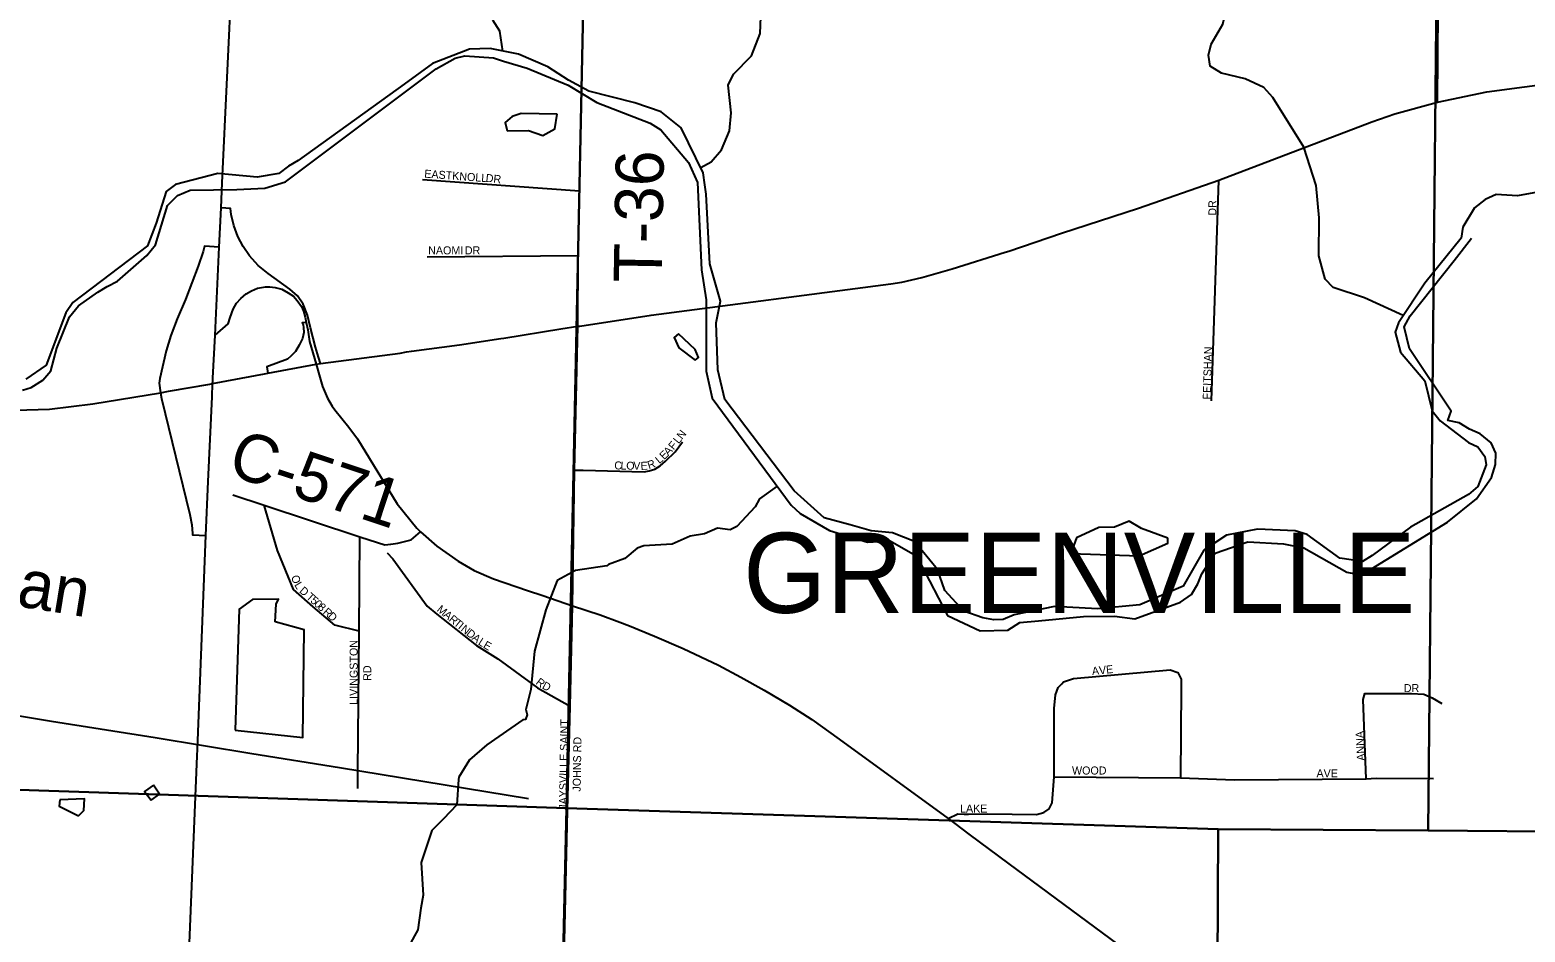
# Model space of a CAD drawing. Extents: x -784 to 1375, y -225 to 440.
# Drawn here: x 321.44 to 357.92, y 339.88 to 361.88 of the extents above; entities that cross this region are included whole.
import ezdxf

# ---------------------------------------------------------------- set-up
doc = ezdxf.new("R2010")
doc.units = 0
for name, color, linetype in [('GM_X_City_Street', 7, 'Continuous'), ('GM_X_City_Street_Text', 7, 'Continuous'), ('GM_X_Corporation_Text', 7, 'Continuous'), ('GM_X_County_Road', 7, 'Continuous'), ('GM_X_County_Road_Text', 7, 'Continuous'), ('GM_X_Interchange_Ramps', 7, 'Continuous'), ('GM_X_Major_River', 7, 'Continuous'), ('GM_X_Minor_Lake', 7, 'Continuous'), ('GM_X_Minor_River', 7, 'Continuous'), ('GM_X_Rail_Line', 7, 'Continuous'), ('GM_X_Rail_Line_Text', 7, 'Continuous'), ('GM_X_Section', 7, 'Continuous'), ('GM_X_State_Route', 7, 'Continuous'), ('GM_X_Township_Road', 7, 'Continuous'), ('GM_X_Township_Road_Text', 7, 'Continuous'), ('GM_X_Township_Subdivision', 7, 'Continuous'), ('GM_X_Township_Subdivision_Text', 7, 'Continuous'), ('GM_X_US_Route', 7, 'Continuous')]:
    doc.layers.add(name, color=color, linetype=linetype)

msp = doc.modelspace()

# ---------------------------------------------------------------- linework, layer by layer
at = {"layer": 'GM_X_City_Street'}
for points in [[(329.476, 347.22), (328.882, 347.364), (328.354, 347.813), (327.878, 348.236), (327.481, 349.187), (327.162, 350.295)], [(329.446, 343.805), (329.446, 343.805), (329.476, 347.22), (329.495, 349.524)], [(330.162, 349.129), (330.3, 348.98), (331.133, 347.832), (331.37, 347.636), (332.342, 346.867), (332.857, 346.544), (333.831, 345.838), (334.623, 345.389)], [(334.563, 342.837), (334.563, 342.856), (334.623, 345.389), (334.681, 347.84)], [(329.443, 343.382), (329.446, 343.805)]]:
    msp.add_lwpolyline(points, dxfattribs=at)
at = {"layer": 'GM_X_County_Road'}
for points in [[(326.397, 350.548), (327.162, 350.295), (329.495, 349.524), (329.927, 349.381), (330.099, 349.325), (330.251, 349.343)], [(330.251, 349.343), (330.251, 349.343), (330.422, 349.363), (330.747, 349.449), (330.975, 349.646)]]:
    msp.add_lwpolyline(points, dxfattribs=at)
at = {"layer": 'GM_X_Interchange_Ramps'}
for points in [[(328.536, 353.745), (328.481, 353.902), (328.408, 354.148), (328.29, 354.618), (328.219, 354.925), (328.111, 355.194), (327.968, 355.4), (327.781, 355.558), (327.257, 355.942), (327.01, 356.141), (326.804, 356.374), (326.648, 356.599), (326.518, 356.844), (326.418, 357.117), (326.354, 357.384), (326.338, 357.531), (326.107, 357.542)], [(326.062, 356.587), (325.7, 356.605), (325.668, 356.48), (325.547, 356.12), (325.24, 355.31), (325.036, 354.833), (324.885, 354.434), (324.764, 354.057), (324.609, 353.379), (324.594, 353.266), (324.625, 353.033)], [(328.179, 354.748), (328.089, 354.743), (328.108, 354.69), (328.118, 354.625), (328.123, 354.502), (328.093, 354.355), (328.015, 354.191), (327.92, 354.04), (327.821, 353.931), (327.728, 353.851), (327.222, 353.667), (327.247, 353.509)], [(324.625, 353.033), (324.653, 352.894), (325.344, 350.063), (325.394, 349.809), (325.413, 349.602), (325.413, 349.571), (325.733, 349.556)]]:
    msp.add_lwpolyline(points, dxfattribs=at)
at = {"layer": 'GM_X_Major_River'}
for points in [[(321.262, 353.1), (321.475, 353.159), (321.754, 353.342), (321.954, 353.565), (322.098, 354.119), (322.411, 354.889), (322.628, 355.151), (323.097, 355.487), (323.327, 355.624), (323.581, 355.752), (324.299, 356.382), (324.508, 356.644), (324.801, 357.602), (325.041, 357.841), (325.35, 357.976), (326.489, 357.994), (327.172, 358.021), (327.678, 358.176), (331.357, 360.936), (331.817, 361.194), (332.053, 361.253), (332.751, 361.201), (333.001, 361.118), (333.579, 360.95), (334.576, 360.532), (335.275, 360.112), (336.577, 359.61), (336.833, 359.449), (337.509, 358.653), (337.735, 358.163), (337.829, 356.031), (337.941, 355.3), (337.94, 353.561), (338.093, 352.9), (340.015, 350.295), (340.239, 350.087), (340.953, 349.674), (341.882, 349.39), (342.432, 349.419), (342.984, 349.103), (343.176, 348.872), (343.835, 347.599), (344.629, 347.231), (345.305, 347.242), (345.599, 347.433), (346.055, 347.471), (347.148, 347.576), (347.902, 347.585), (348.403, 347.521), (349.518, 347.923), (349.788, 348.114), (349.935, 348.378), (350.033, 348.619), (350.365, 349.122), (351.155, 349.397), (352.026, 349.349), (352.526, 349.253), (353.575, 348.661), (353.786, 348.618), (354.07, 348.675), (356.032, 349.876), (356.741, 350.45), (357.104, 350.968), (357.204, 351.288), (357.21, 351.562), (357.096, 351.815), (356.826, 352.031), (356.569, 352.146), (356.313, 352.3), (356.039, 352.36), (356.122, 352.586), (355.106, 354.109), (354.975, 354.645), (355.121, 354.908), (356.19, 356.259), (356.617, 356.807)], [(358.539, 357.985), (357.735, 357.836), (357.217, 357.869), (356.948, 357.749), (356.693, 357.542), (356.402, 357.07), (356.365, 356.804), (355.481, 355.708), (354.835, 354.741), (354.752, 354.508), (354.885, 354.027), (355.476, 353.327), (355.659, 352.594), (355.85, 352.348), (356.547, 351.817), (356.773, 351.719), (356.941, 351.481), (356.976, 351.276), (356.77, 350.747), (356.547, 350.556), (355.127, 349.76), (354.195, 349.065), (353.957, 348.92), (353.401, 349.001), (352.603, 349.581), (352.314, 349.665), (351.396, 349.706), (350.64, 349.563), (350.083, 349.197), (349.58, 348.314), (348.527, 347.863), (347.489, 347.765), (346.438, 347.824), (345.461, 347.615), (345.192, 347.503), (344.964, 347.499), (344.69, 347.544), (344.23, 347.709), (343.768, 348.211), (343.589, 348.724), (343.029, 349.408), (342.491, 349.614), (341.966, 349.663), (341.458, 349.813), (340.825, 349.982), (340.092, 350.646), (338.398, 352.871), (338.231, 353.595), (338.19, 354.739), (338.294, 355.27), (338.036, 356.176), (337.942, 357.877), (337.907, 358.105), (337.873, 358.396), (337.336, 359.495), (336.841, 359.888), (336.201, 360.103), (335.076, 360.39), (334.586, 360.658), (334.082, 360.98), (333.365, 361.291), (332.669, 361.429), (332.166, 361.415), (331.265, 361.063), (330.572, 360.559), (327.986, 358.695), (327.755, 358.559), (327.517, 358.383), (326.989, 358.291), (326.025, 358.379), (324.991, 358.116), (324.768, 357.94), (324.526, 357.169), (324.312, 356.616), (322.488, 355.232), (322.318, 354.984), (321.839, 353.708), (321.346, 353.365)]]:
    msp.add_lwpolyline(points, dxfattribs=at)
at = {"layer": 'GM_X_Minor_Lake'}
for points in [[(334.304, 359.832), (333.425, 359.841), (333.211, 359.774), (333.036, 359.621), (333.087, 359.424)], [(333.087, 359.424), (333.606, 359.43), (333.957, 359.306), (334.25, 359.473), (334.304, 359.832)], [(337.266, 354.474), (337.162, 354.382), (337.275, 354.129), (337.678, 353.832)], [(337.678, 353.832), (337.758, 353.893), (337.675, 354.091), (337.266, 354.474)], [(349.21, 349.488), (348.562, 349.72), (348.267, 349.906), (347.903, 349.756), (347.526, 349.747), (346.98, 349.499), (346.839, 349.11)], [(346.839, 349.11), (348.51, 349.055), (349.207, 349.363), (349.21, 349.488)], [(327.43, 347.448), (327.454, 347.879), (327.504, 348.003), (326.875, 347.991), (326.549, 347.754), (326.454, 344.802)], [(326.454, 344.802), (328.1, 344.623), (328.133, 347.255), (327.43, 347.448)], [(324.459, 343.46), (324.236, 343.308), (324.405, 343.101)], [(324.405, 343.101), (324.604, 343.246), (324.459, 343.46)], [(322.175, 343.103), (322.156, 342.954), (322.631, 342.718)], [(322.631, 342.718), (322.759, 342.849), (322.772, 343.131), (322.175, 343.103)]]:
    msp.add_lwpolyline(points, dxfattribs=at)
at = {"layer": 'GM_X_Minor_River'}
for points in [[(337.81, 358.525), (338.062, 358.666), (338.316, 358.955), (338.512, 359.419), (338.551, 359.858), (338.481, 360.536), (338.608, 360.806), (339.048, 361.254), (339.263, 361.796), (339.314, 363.239), (339.166, 363.958), (339.205, 364.169), (339.568, 364.659), (340.038, 365.058), (340.203, 365.296), (340.266, 365.537), (340.313, 365.739), (340.572, 365.966), (341.044, 366.216), (341.21, 366.469), (341.29, 366.726), (341.229, 367.003), (341.27, 367.284), (341.436, 367.545)], [(354.952, 354.917), (354.007, 355.345), (353.239, 355.6), (353.049, 355.804), (352.889, 356.375), (352.898, 357.301), (352.823, 358.089), (352.526, 359.026), (351.767, 360.231), (351.548, 360.482), (351.092, 360.687), (350.516, 360.825), (350.239, 361), (350.201, 361.268), (350.265, 361.533), (350.55, 362.025), (350.643, 362.446), (350.61, 363.507), (350.411, 363.907), (350.24, 364.18), (349.77, 364.804)], [(332.98, 361.368), (332.907, 361.853), (332.736, 362.118)], [(339.676, 350.754), (339.248, 350.447), (339.139, 350.251), (338.687, 349.773), (338.531, 349.695), (338.218, 349.733), (337.898, 349.592), (337.554, 349.536), (337.117, 349.34), (336.421, 349.3), (336.257, 349.245), (335.96, 348.993), (335.562, 348.844), (335.515, 348.813), (334.757, 348.702), (334.304, 348.453)], [(334.304, 348.453), (334.032, 347.737), (333.753, 346.735), (333.662, 345.795), (333.546, 345.31), (333.577, 345.177), (333.531, 345.067), (333.468, 345.059), (332.594, 344.447), (332.165, 344.078), (331.908, 343.655), (331.9, 343.6), (331.863, 342.982), (331.535, 342.645), (331.247, 342.362), (330.99, 341.579), (331.039, 340.78), (330.977, 340.467), (330.908, 339.935), (330.698, 339.551), (330.433, 339.245), (329.902, 338.868), (329.726, 338.681)]]:
    msp.add_lwpolyline(points, dxfattribs=at)
at = {"layer": 'GM_X_Rail_Line'}
msp.add_lwpolyline([(303.626, 348.002), (306.309, 347.573), (311.473, 346.733), (313.943, 346.334), (317.442, 345.777), (321.968, 345.028), (324.501, 344.623), (326.856, 344.239), (328.997, 343.894), (333.611, 343.138)], dxfattribs=at)
at = {"layer": 'GM_X_Section'}
for points in [[(314.451, 364.338), (334.976, 363.947), (334.534, 342.899), (313.882, 343.598)], [(334.976, 363.947), (355.77, 363.658), (355.556, 342.355), (350.439, 342.394), (334.534, 342.899)], [(313.882, 343.598), (334.534, 342.899), (334.074, 322.46), (313.315, 322.896)], [(334.534, 342.899), (350.439, 342.394), (350.336, 322.182), (334.071, 322.32), (334.074, 322.46)], [(350.439, 342.394), (355.556, 342.355), (370.946, 342.229), (370.866, 322.002), (350.336, 322.182)]]:
    msp.add_lwpolyline(points, close=True, dxfattribs=at)
msp.add_lwpolyline([(374.961, 342.202), (370.946, 342.229), (355.556, 342.355), (355.77, 363.658), (374.961, 363.509)], dxfattribs=at)
at = {"layer": 'GM_X_State_Route'}
for points in [[(325.836, 353.247), (325.901, 353.258), (327.164, 353.494), (327.247, 353.509), (328.427, 353.728)], [(328.427, 353.728), (328.497, 353.472), (328.582, 353.183), (328.701, 352.898), (328.815, 352.704), (328.885, 352.616)], [(324.827, 353.069), (325.836, 353.247)], [(318.89, 352.636), (319.037, 352.622), (319.968, 352.575), (321.923, 352.637), (322.974, 352.76), (324.625, 353.033), (324.827, 353.069)], [(328.885, 352.616), (329.053, 352.403), (329.226, 352.192), (329.439, 351.91), (330.406, 350.323), (330.881, 349.732), (330.975, 349.646), (331.37, 349.29), (331.894, 348.93), (332.281, 348.703), (332.751, 348.494), (333.586, 348.215)], [(333.586, 348.215), (333.959, 348.09), (334.681, 347.84), (335.36, 347.619), (335.835, 347.439)], [(335.835, 347.439), (336.076, 347.347), (336.679, 347.1), (337.384, 346.797), (338.245, 346.39), (338.789, 346.101), (339.357, 345.781), (339.973, 345.413), (340.517, 345.068), (341.186, 344.589), (343.846, 342.655), (344.013, 342.528)], [(344.013, 342.528), (344.349, 342.273), (345.326, 341.547), (353.126, 335.782)]]:
    msp.add_lwpolyline(points, dxfattribs=at)
at = {"layer": 'GM_X_Township_Road'}
for points in [[(355.783, 360.117), (355.804, 362.373), (355.882, 370.725), (356.105, 384.217)], [(334.681, 347.84), (334.731, 351.148), (334.814, 354.657), (334.82, 356.384), (334.852, 357.958), (334.948, 362.619), (335.022, 366.247), (335.053, 367.767), (335.118, 370.955)], [(334.37, 334.707), (334.37, 334.721), (334.563, 342.837)]]:
    msp.add_lwpolyline(points, dxfattribs=at)
at = {"layer": 'GM_X_Township_Subdivision'}
for points in [[(331.022, 358.231), (334.852, 357.958)], [(350.269, 352.836), (350.452, 358.219)], [(331.133, 356.347), (334.82, 356.384)], [(334.94, 351.143), (336.433, 351.104), (336.555, 351.126), (336.693, 351.169), (336.82, 351.255), (336.954, 351.363), (337.183, 351.593), (337.367, 351.837)], [(334.731, 351.148), (334.94, 351.143)], [(346.618, 345.934), (346.661, 345.98), (346.904, 346.068), (349.264, 346.28), (349.455, 346.21), (349.529, 346.047), (349.536, 345.838), (349.516, 343.646)], [(344.239, 342.76), (344.345, 342.758), (344.817, 342.762), (346.005, 342.752), (346.18, 342.796), (346.314, 342.886), (346.387, 343.03), (346.431, 343.666), (346.437, 345.33), (346.465, 345.668), (346.532, 345.844), (346.618, 345.934)], [(354.048, 343.619), (353.976, 345.557), (354.011, 345.698), (355.152, 345.696), (355.451, 345.687), (355.66, 345.595), (355.892, 345.455)], [(346.431, 343.666), (349.516, 343.646), (350.835, 343.592), (354.048, 343.619), (354.292, 343.632), (355.686, 343.625)], [(343.846, 342.655), (344.084, 342.762), (344.239, 342.76)]]:
    msp.add_lwpolyline(points, dxfattribs=at)
at = {"layer": 'GM_X_US_Route'}
for points in [[(326.136, 358.154), (326.746, 371.004), (326.756, 371.206)], [(355.783, 360.117), (356.993, 360.375), (358.826, 360.615), (360.836, 360.842)], [(345.237, 356.459), (345.324, 356.487), (346.616, 356.924), (348.494, 357.534), (350.452, 358.219), (354.184, 359.638), (354.748, 359.84), (355.783, 360.117)], [(325.96, 354.44), (326.062, 356.587), (326.107, 357.542), (326.136, 358.154)], [(334.814, 354.657), (334.859, 354.658), (336.603, 354.927), (342.446, 355.687), (342.713, 355.73), (343.201, 355.846), (343.944, 356.053), (345.237, 356.459)], [(325.96, 354.44), (326.281, 354.718), (326.327, 354.871), (326.4, 355.074), (326.484, 355.219), (326.587, 355.334), (326.717, 355.448), (326.847, 355.521), (326.997, 355.586), (327.192, 355.617), (327.299, 355.617), (327.425, 355.598), (327.591, 355.562), (327.743, 355.471), (327.873, 355.387), (327.961, 355.28), (328.072, 355.135), (328.117, 355.024), (328.156, 354.878), (328.179, 354.748), (328.225, 354.572), (328.267, 354.286), (328.427, 353.728)], [(334.396, 354.59), (334.814, 354.657)], [(325.904, 353.313), (325.908, 353.389), (325.96, 354.44)], [(330.631, 354.029), (330.753, 354.049), (331.923, 354.205), (332.935, 354.355)], [(332.935, 354.355), (333.006, 354.366), (334.396, 354.59)], [(328.427, 353.728), (328.536, 353.745), (330.474, 354.003), (330.631, 354.029)], [(325.887, 352.937), (325.901, 353.258), (325.904, 353.313)], [(325.793, 350.871), (325.887, 352.937)], [(325.53, 344.343), (325.733, 349.556), (325.793, 350.871)], [(322.649, 322.812), (323.385, 324.433), (324.063, 326.299), (324.565, 328.307), (324.802, 329.645), (324.961, 331.044), (325.084, 333.456), (325.524, 344.176), (325.53, 344.343)]]:
    msp.add_lwpolyline(points, dxfattribs=at)

# ---------------------------------------------------------------- texts
at = {"layer": 'GM_X_City_Street_Text'}
for s, height, rotation, p in [('O', 0.195, 290.07, (327.809, 348.546)), ('L', 0.195, 301.0147, (327.886, 348.348)), ('D', 0.195, 319.4722, (328.001, 348.178)), ('T', 0.195, 318.1214, (328.169, 348.033)), ('5', 0.195, 318.1175, (328.271, 347.941)), ('0', 0.195, 318.1175, (328.361, 347.86)), ('8', 0.195, 318.1175, (328.45, 347.78)), ('R', 0.195, 318.1199, (328.578, 347.665)), ('D', 0.195, 318.121, (328.693, 347.562)), ('M', 0.195, 320.8993, (331.355, 347.72)), ('A', 0.195, 320.8998, (331.515, 347.59)), ('R', 0.195, 320.8984, (331.648, 347.482)), ('T', 0.195, 320.9024, (331.768, 347.384)), ('I', 0.195, 320.8897, (331.875, 347.297)), ('N', 0.195, 320.9117, (331.942, 347.243)), ('LIVINGSTON', 0.1953, 90, (329.439, 345.423)), ('D', 0.195, 320.9067, (332.075, 347.135)), ('A', 0.195, 321.6367, (332.211, 347.025)), ('L', 0.195, 327.3698, (332.363, 346.906)), ('E', 0.195, 329.4362, (332.485, 346.827)), ('RD', 0.1953, 90, (329.771, 346.008)), ('R', 0.195, 322.4136, (333.769, 345.943)), ('D', 0.195, 332.9601, (333.924, 345.828)), ('JAYSVILLE SAINT', 0.19531, 89.029, (334.544, 342.863)), ('JOHNS RD', 0.1953, 89.1316, (334.88, 343.305))]:
    msp.add_text(s, height=height, rotation=rotation, dxfattribs=at).set_placement(p)
at = {"layer": 'GM_X_Corporation_Text'}
msp.add_text('GREENVILLE', height=1.9531, rotation=0, dxfattribs=at).set_placement((338.845, 347.666))
at = {"layer": 'GM_X_County_Road_Text'}
msp.add_text('C-571', height=1.1719, rotation=341.7156, dxfattribs=at).set_placement((326.223, 351.053))
at = {"layer": 'GM_X_Rail_Line_Text'}
msp.add_text('R.J. Corman', height=1.16797, rotation=350.7396, dxfattribs=at).set_placement((314.155, 348.969))
at = {"layer": 'GM_X_Township_Road_Text'}
msp.add_text('T-36', height=1.1719, rotation=88.9531, dxfattribs=at).set_placement((336.855, 355.713))
at = {"layer": 'GM_X_Township_Subdivision_Text'}
for s, height, rotation, p in [('EASTKNOLL', 0.1953, 355.8147, (331.06, 358.282)), ('DR', 0.1953, 353.9943, (332.556, 358.179)), ('DR', 0.1953, 90, (350.391, 357.352)), ('NAOMI', 0.1953, 0, (331.16, 356.409)), ('DR', 0.1953, 0, (332.054, 356.409)), ('FEITSHAN', 0.1953, 88.2912, (350.253, 352.867)), ('N', 0.195, 51.5556, (337.358, 351.882)), ('A', 0.195, 45.9711, (337.019, 351.489)), ('F', 0.195, 50.2385, (337.149, 351.625)), ('L', 0.195, 51.531, (337.272, 351.775)), ('C', 0.195, 358.7856, (335.699, 351.166)), ('L', 0.195, 358.8115, (335.853, 351.163)), ('O', 0.195, 358.7977, (335.991, 351.16)), ('V', 0.195, 358.7977, (336.163, 351.157)), ('E', 0.195, 1.5825, (336.345, 351.153)), ('R', 0.195, 18.7984, (336.545, 351.168)), ('L', 0.195, 40.3028, (336.8, 351.29)), ('E', 0.195, 44.1237, (336.916, 351.389)), ('AVE', 0.1953, 5.9031, (347.364, 346.147)), ('DR', 0.1953, 0, (354.965, 345.734)), ('ANNA', 0.1953, 92.8638, (354.018, 344.064)), ('WOOD', 0.1953, 0, (346.869, 343.724)), ('AVE', 0.1953, 0, (352.834, 343.655)), ('LAKE', 0.1953, 0, (344.137, 342.796))]:
    msp.add_text(s, height=height, rotation=rotation, dxfattribs=at).set_placement(p)

doc.saveas('drawing.dxf')
